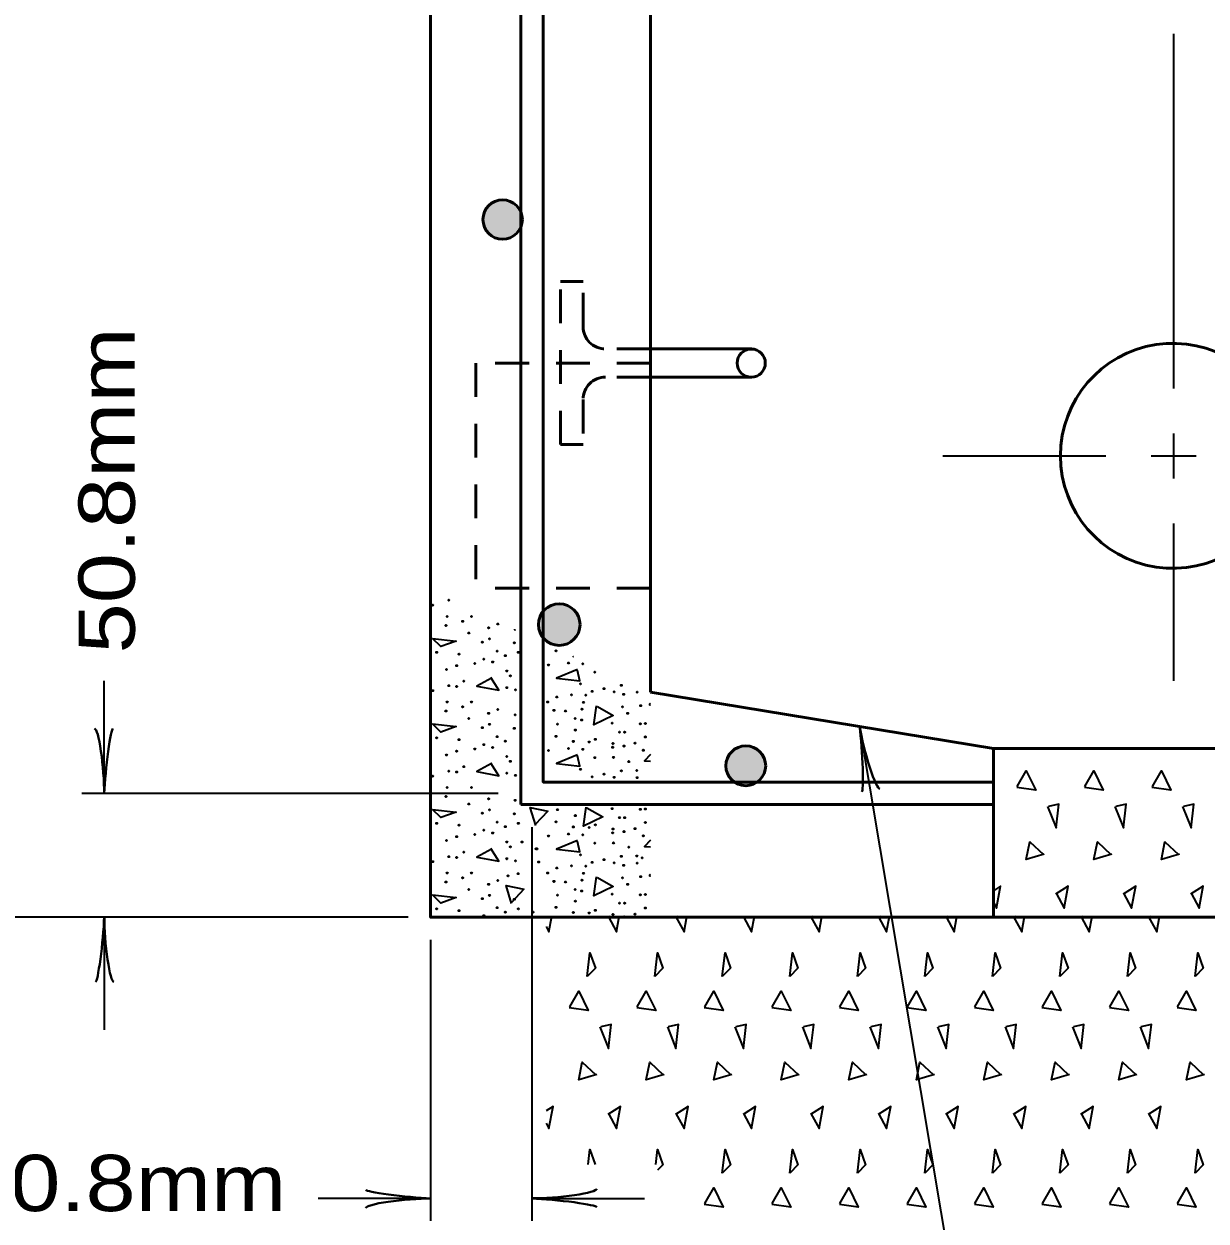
# Model space of a CAD drawing. Extents: x 918 to 1774, y -8 to 536.
# Drawn here: x 1039.5 to 1102.6, y 129.8 to 193.7 of the extents above; entities that cross this region are included whole.
import ezdxf

# ---------------------------------------------------------------- set-up
doc = ezdxf.new("R2010")
doc.units = 0
doc.header["$LTSCALE"] = 1.2
doc.linetypes.add('SHORT_DASHED', pattern=[2.7, 1.5, -1.2])
doc.layers.add('1', color=7, linetype='Continuous', lineweight=35)

msp = doc.modelspace()

# ---------------------------------------------------------------- hatches: boundary and pattern name
at = {"layer": '1'}
for points in [[(1066.115, 183.245, 1), (1064.014, 183.245, 1)], [(1069.19, 161.645, 1), (1066.973, 161.645, 1)], [(1079.087, 154.116, 1), (1076.963, 154.116, 1)]]:
    msp.add_hatch(color=256, dxfattribs=at).paths.add_polyline_path(points)

# ---------------------------------------------------------------- linework, layer by layer
at = {"layer": '1', "lineweight": 53}
for p, q in [((1061.227, 198.122), (1061.227, 163.476)), ((1072.952, 198.122), (1072.952, 158.043)), ((1072.952, 176.343), (1078.351, 176.343)), ((1072.952, 174.843), (1078.351, 174.843)), ((1072.952, 158.043), (1091.227, 155.043)), ((1091.227, 155.043), (1110.428, 155.043)), ((1091.227, 155.043), (1091.227, 146.043)), ((1072.952, 146.043), (1127.291, 146.043))]:
    msp.add_line(p, q, dxfattribs=at)
at = {"layer": '1'}
for p, q in [((1100.828, 193.143), (1100.828, 174.243)), ((1100.828, 171.843), (1100.828, 169.443)), ((1088.528, 170.643), (1097.227, 170.643)), ((1099.628, 170.643), (1102.028, 170.643)), ((1100.828, 167.043), (1100.828, 158.643)), ((1043.828, 152.643), (1043.828, 158.643)), ((1064.828, 152.643), (1042.628, 152.643)), ((1066.628, 150.843), (1066.628, 129.843)), ((1060.028, 146.043), (1028.227, 146.043)), ((1043.828, 146.043), (1043.828, 140.043)), ((1070.8, 146.086), (1070.678, 146.007)), ((1074.4, 146.086), (1074.278, 146.007)), ((1078, 146.086), (1077.878, 146.007)), ((1081.6, 146.086), (1081.478, 146.007)), ((1085.2, 146.086), (1085.078, 146.007)), ((1088.8, 146.086), (1088.678, 146.007)), ((1092.4, 146.086), (1092.278, 146.007)), ((1096, 146.086), (1095.878, 146.007)), ((1099.6, 146.086), (1099.478, 146.007)), ((1061.227, 144.843), (1061.227, 129.843)), ((1061.227, 131.043), (1055.227, 131.043)), ((1066.628, 131.043), (1072.628, 131.043))]:
    msp.add_line(p, q, dxfattribs=at)
at = {"layer": '1', "linetype": 'SHORT_DASHED', "lineweight": 53}
for p, q in [((1069.351, 177.543), (1069.351, 179.943)), ((1072.952, 176.343), (1070.552, 176.343)), ((1072.952, 175.593), (1063.64, 175.593)), ((1063.64, 175.593), (1063.64, 163.593)), ((1072.952, 174.843), (1070.552, 174.843)), ((1069.351, 173.643), (1069.351, 171.243)), ((1068.151, 171.243), (1069.351, 171.243)), ((1072.952, 163.593), (1063.64, 163.593))]:
    msp.add_line(p, q, dxfattribs=at)
at = {"layer": '1', "lineweight": 53}
msp.add_lwpolyline([(1066.028, 152.043), (1066.028, 224.745), (1067.227, 224.745), (1067.227, 153.243), (1091.227, 153.243), (1091.227, 152.043)], close=True, dxfattribs=at)
at = {"layer": '1', "linetype": 'SHORT_DASHED', "lineweight": 53}
msp.add_lwpolyline([(1068.151, 171.243), (1068.151, 179.943), (1069.351, 179.943)], dxfattribs=at)
at = {"layer": '1', "lineweight": 53}
msp.add_lwpolyline([(1072.952, 146.043), (1061.227, 146.043), (1061.227, 163.476)], dxfattribs=at)
at = {"layer": '1'}
for points in [[(1061.227, 163.452), (1061.235, 163.452), (1061.227, 163.468)], [(1069.059, 159.252), (1067.931, 158.796), (1069.179, 158.652), (1069.059, 159.204)], [(1061.227, 158.892), (1061.235, 158.892), (1061.227, 158.908)], [(1064.475, 158.796), (1063.683, 158.364), (1064.859, 158.148), (1064.427, 158.82)], [(1070.115, 157.284), (1070.955, 156.804), (1069.923, 156.3), (1070.067, 157.308)], [(1084.092, 156.215), (1093.824, 98.076), (1086.695, 98.076)], [(1069.059, 154.692), (1067.931, 154.236), (1069.179, 154.092), (1069.059, 154.644)], [(1072.952, 154.713), (1072.635, 154.38), (1072.952, 154.358)], [(1061.227, 154.332), (1061.235, 154.332), (1061.227, 154.348)], [(1064.475, 154.236), (1063.683, 153.804), (1064.859, 153.588), (1064.427, 154.26)], [(1092.5, 153.007), (1092.98, 153.847), (1093.484, 152.815), (1092.476, 152.959)], [(1096.1, 153.007), (1096.58, 153.847), (1097.084, 152.815), (1096.076, 152.959)], [(1099.7, 153.007), (1100.18, 153.847), (1100.684, 152.815), (1099.676, 152.959)], [(1094.108, 151.951), (1094.564, 150.799), (1094.708, 152.071), (1094.156, 151.951)], [(1097.708, 151.951), (1098.164, 150.799), (1098.308, 152.071), (1097.756, 151.951)], [(1101.308, 151.951), (1101.764, 150.799), (1101.908, 152.071), (1101.356, 151.951)], [(1066.828, 150.929), (1066.54, 151.889), (1067.476, 151.697), (1066.804, 150.977)], [(1069.561, 151.88), (1070.4, 151.4), (1069.369, 150.896), (1069.513, 151.904)], [(1069.059, 150.132), (1067.931, 149.676), (1069.179, 149.532), (1069.059, 150.084)], [(1072.952, 150.153), (1072.635, 149.82), (1072.952, 149.798)], [(1093.94, 149.406), (1092.98, 149.119), (1093.172, 150.055), (1093.892, 149.382)], [(1097.54, 149.406), (1096.58, 149.119), (1096.772, 150.055), (1097.492, 149.382)], [(1101.14, 149.406), (1100.18, 149.119), (1100.372, 150.055), (1101.092, 149.382)], [(1061.227, 149.772), (1061.235, 149.772), (1061.227, 149.788)], [(1064.475, 149.676), (1063.683, 149.244), (1064.859, 149.028), (1064.427, 149.7)], [(1070.115, 148.164), (1070.955, 147.684), (1069.923, 147.18), (1070.067, 148.188)], [(1065.541, 146.768), (1065.253, 147.728), (1066.189, 147.536), (1065.517, 146.816)], [(1091.227, 146.836), (1091.396, 146.526), (1091.612, 147.703), (1091.227, 147.455)], [(1094.564, 147.319), (1094.996, 146.526), (1095.212, 147.703), (1094.54, 147.27)], [(1098.164, 147.319), (1098.596, 146.526), (1098.812, 147.703), (1098.14, 147.27)], [(1101.764, 147.319), (1102.196, 146.526), (1102.412, 147.703), (1101.74, 147.27)], [(1067.382, 145.542), (1067.534, 145.263), (1067.685, 146.086)], [(1070.702, 146.055), (1071.134, 145.263), (1071.285, 146.086)], [(1074.302, 146.055), (1074.734, 145.263), (1074.885, 146.086)], [(1077.902, 146.055), (1078.334, 145.263), (1078.485, 146.086)], [(1081.502, 146.055), (1081.934, 145.263), (1082.085, 146.086)], [(1085.102, 146.055), (1085.534, 145.263), (1085.685, 146.086)], [(1088.702, 146.055), (1089.134, 145.263), (1089.285, 146.086)], [(1092.302, 146.055), (1092.734, 145.263), (1092.885, 146.086)], [(1095.902, 146.055), (1096.334, 145.263), (1096.485, 146.086)], [(1099.502, 146.055), (1099.934, 145.263), (1100.085, 146.086)], [(1068.638, 141.255), (1069.118, 142.095), (1069.622, 141.063), (1068.614, 141.207)], [(1072.238, 141.255), (1072.718, 142.095), (1073.222, 141.063), (1072.214, 141.207)], [(1075.838, 141.255), (1076.318, 142.095), (1076.822, 141.063), (1075.814, 141.207)], [(1079.438, 141.255), (1079.918, 142.095), (1080.422, 141.063), (1079.414, 141.207)], [(1083.038, 141.255), (1083.518, 142.095), (1084.022, 141.063), (1083.014, 141.207)], [(1086.638, 141.255), (1087.118, 142.095), (1087.622, 141.063), (1086.614, 141.207)], [(1090.238, 141.255), (1090.718, 142.095), (1091.222, 141.063), (1090.214, 141.207)], [(1093.838, 141.255), (1094.318, 142.095), (1094.822, 141.063), (1093.814, 141.207)], [(1097.438, 141.255), (1097.918, 142.095), (1098.422, 141.063), (1097.414, 141.207)], [(1101.038, 141.255), (1101.518, 142.095), (1102.022, 141.063), (1101.014, 141.207)], [(1070.246, 140.199), (1070.702, 139.047), (1070.846, 140.319), (1070.294, 140.199)], [(1073.846, 140.199), (1074.302, 139.047), (1074.446, 140.319), (1073.894, 140.199)], [(1077.446, 140.199), (1077.902, 139.047), (1078.046, 140.319), (1077.494, 140.199)], [(1081.046, 140.199), (1081.502, 139.047), (1081.646, 140.319), (1081.094, 140.199)], [(1084.646, 140.199), (1085.102, 139.047), (1085.246, 140.319), (1084.694, 140.199)], [(1088.246, 140.199), (1088.702, 139.047), (1088.846, 140.319), (1088.294, 140.199)], [(1091.846, 140.199), (1092.302, 139.047), (1092.446, 140.319), (1091.894, 140.199)], [(1095.446, 140.199), (1095.902, 139.047), (1096.046, 140.319), (1095.494, 140.199)], [(1099.046, 140.199), (1099.502, 139.047), (1099.646, 140.319), (1099.094, 140.199)], [(1070.078, 137.655), (1069.118, 137.367), (1069.31, 138.303), (1070.03, 137.631)], [(1073.678, 137.655), (1072.718, 137.367), (1072.91, 138.303), (1073.63, 137.631)], [(1077.278, 137.655), (1076.318, 137.367), (1076.51, 138.303), (1077.23, 137.631)], [(1080.878, 137.655), (1079.918, 137.367), (1080.11, 138.303), (1080.83, 137.631)], [(1084.478, 137.655), (1083.518, 137.367), (1083.71, 138.303), (1084.43, 137.631)], [(1088.078, 137.655), (1087.118, 137.367), (1087.31, 138.303), (1088.03, 137.631)], [(1091.678, 137.655), (1090.718, 137.367), (1090.91, 138.303), (1091.63, 137.631)], [(1095.278, 137.655), (1094.318, 137.367), (1094.51, 138.303), (1095.23, 137.631)], [(1098.878, 137.655), (1097.918, 137.367), (1098.11, 138.303), (1098.83, 137.631)], [(1102.478, 137.655), (1101.518, 137.367), (1101.71, 138.303), (1102.43, 137.631)], [(1067.382, 135.054), (1067.534, 134.775), (1067.75, 135.951), (1067.382, 135.715)], [(1070.702, 135.567), (1071.134, 134.775), (1071.35, 135.951), (1070.678, 135.519)], [(1074.302, 135.567), (1074.734, 134.775), (1074.95, 135.951), (1074.278, 135.519)], [(1077.902, 135.567), (1078.334, 134.775), (1078.55, 135.951), (1077.878, 135.519)], [(1081.502, 135.567), (1081.934, 134.775), (1082.15, 135.951), (1081.478, 135.519)], [(1085.102, 135.567), (1085.534, 134.775), (1085.75, 135.951), (1085.078, 135.519)], [(1088.702, 135.567), (1089.134, 134.775), (1089.35, 135.951), (1088.678, 135.519)], [(1092.302, 135.567), (1092.734, 134.775), (1092.95, 135.951), (1092.278, 135.519)], [(1095.902, 135.567), (1096.334, 134.775), (1096.55, 135.951), (1095.878, 135.519)], [(1099.502, 135.567), (1099.934, 134.775), (1100.15, 135.951), (1099.478, 135.519)], [(1069.626, 132.853), (1069.718, 133.647), (1069.998, 132.853)], [(1073.226, 132.853), (1073.318, 133.647), (1073.606, 132.831), (1073.322, 132.547)], [(1075.838, 130.767), (1076.318, 131.607), (1076.822, 130.575), (1075.814, 130.719)], [(1079.438, 130.767), (1079.918, 131.607), (1080.422, 130.575), (1079.414, 130.719)], [(1083.038, 130.767), (1083.518, 131.607), (1084.022, 130.575), (1083.014, 130.719)], [(1086.638, 130.767), (1087.118, 131.607), (1087.622, 130.575), (1086.614, 130.719)], [(1090.238, 130.767), (1090.718, 131.607), (1091.222, 130.575), (1090.214, 130.719)], [(1093.838, 130.767), (1094.318, 131.607), (1094.822, 130.575), (1093.814, 130.719)], [(1097.438, 130.767), (1097.918, 131.607), (1098.422, 130.575), (1097.414, 130.719)], [(1101.038, 130.767), (1101.518, 131.607), (1102.022, 130.575), (1101.014, 130.719)]]:
    msp.add_lwpolyline(points, dxfattribs=at)
for points in [[(1061.331, 160.908), (1062.579, 160.764), (1061.763, 160.476)], [(1061.331, 156.348), (1062.579, 156.204), (1061.763, 155.916)], [(1061.331, 151.788), (1062.579, 151.644), (1061.763, 151.356)], [(1061.331, 147.228), (1062.579, 147.084), (1061.763, 146.796)], [(1069.574, 142.887), (1069.718, 144.135), (1070.006, 143.319)], [(1073.174, 142.887), (1073.318, 144.135), (1073.606, 143.319)], [(1076.774, 142.887), (1076.918, 144.135), (1077.206, 143.319)], [(1080.374, 142.887), (1080.518, 144.135), (1080.806, 143.319)], [(1083.974, 142.887), (1084.118, 144.135), (1084.406, 143.319)], [(1087.574, 142.887), (1087.718, 144.135), (1088.006, 143.319)], [(1091.174, 142.887), (1091.318, 144.135), (1091.606, 143.319)], [(1094.774, 142.887), (1094.918, 144.135), (1095.206, 143.319)], [(1098.374, 142.887), (1098.518, 144.135), (1098.806, 143.319)], [(1101.974, 142.887), (1102.118, 144.135), (1102.406, 143.319)], [(1076.774, 132.399), (1076.918, 133.647), (1077.206, 132.831)], [(1080.374, 132.399), (1080.518, 133.647), (1080.806, 132.831)], [(1083.974, 132.399), (1084.118, 133.647), (1084.406, 132.831)], [(1087.574, 132.399), (1087.718, 133.647), (1088.006, 132.831)], [(1091.174, 132.399), (1091.318, 133.647), (1091.606, 132.831)], [(1094.774, 132.399), (1094.918, 133.647), (1095.206, 132.831)], [(1098.374, 132.399), (1098.518, 133.647), (1098.806, 132.831)], [(1101.974, 132.399), (1102.118, 133.647), (1102.406, 132.831)]]:
    msp.add_lwpolyline(points, close=True, dxfattribs=at)
at = {"layer": '1', "lineweight": 53}
for centre, radius in [((1065.065, 183.245), 1.05), ((1078.317, 175.591), 0.75), ((1068.082, 161.645), 1.109), ((1078.025, 154.116), 1.062)]:
    msp.add_circle(centre, radius, dxfattribs=at)
at = {"layer": '1'}
for centre in [(1062.2, 162.951), (1061.341, 162.68), (1062.041, 161.599), (1062.104, 162.076), (1062.931, 161.821), (1063.408, 162.076), (1064.808, 161.678), (1063.265, 161.201), (1064.315, 161.471), (1064.363, 160.883), (1063.981, 160.708), (1064.776, 160.23), (1065.683, 160.676), (1067.909, 160.246), (1061.548, 160.167), (1062.74, 160.071), (1064.06, 159.801), (1064.537, 159.648), (1065.205, 159.992), (1065.905, 160.167), (1068.577, 159.6), (1062.072, 159.25), (1062.613, 159.457), (1063.583, 159.568), (1065.285, 159.17), (1067.511, 159.489), (1069.34, 159.552), (1069.977, 159.107), (1062.2, 158.391), (1062.613, 158.343), (1062.995, 158.63), (1065.476, 158.916), (1069.213, 158.486), (1071.392, 158.407), (1061.341, 158.12), (1065.285, 158.279), (1065.746, 158.168), (1067.957, 157.786), (1068.736, 157.898), (1069.499, 157.882), (1069.833, 158.089), (1070.47, 158.232), (1071.01, 158.057), (1071.519, 157.929), (1072.235, 158.041), (1062.041, 157.039), (1062.104, 157.516), (1062.931, 157.261), (1063.408, 157.516), (1064.808, 157.118), (1067.464, 157.516), (1067.798, 157.07), (1068.418, 157.039), (1069.293, 157.134), (1069.372, 157.5), (1071.456, 157.261), (1072.426, 157.325), (1063.265, 156.641), (1064.315, 156.911), (1065.73, 156.832), (1068.927, 156.641), (1069.277, 156.561), (1070.899, 156.386), (1071.726, 156.911), (1063.981, 156.148), (1064.363, 156.323), (1065.683, 156.116), (1067.989, 156.339), (1068.943, 156.02), (1071.297, 155.909), (1071.567, 155.909), (1072.402, 156.352), (1072.673, 156.37), (1061.548, 155.607), (1062.74, 155.511), (1064.06, 155.241), (1064.776, 155.67), (1065.205, 155.432), (1067.909, 155.686), (1068.832, 155.416), (1069.674, 155.384), (1070.008, 155.527), (1070.931, 155.104), (1070.947, 155.305), (1071.535, 155.167), (1072.124, 155.32), (1072.673, 155.655), (1062.072, 154.69), (1062.613, 154.897), (1063.583, 155.008), (1064.537, 155.088), (1065.285, 154.61), (1067.511, 154.929), (1068.577, 155.04), (1069.34, 154.992), (1069.977, 154.547), (1070.978, 154.563), (1072.562, 154.944), (1062.2, 153.831), (1062.995, 154.07), (1065.476, 154.356), (1069.213, 153.926), (1071.392, 153.847), (1071.79, 154.34), (1072.219, 153.863), (1061.341, 153.56), (1062.613, 153.783), (1065.285, 153.719), (1065.746, 153.608), (1069.833, 153.529), (1070.47, 153.672), (1071.01, 153.497), (1072.235, 153.481), (1062.104, 152.956), (1063.408, 152.956), (1062.041, 152.479), (1063.265, 152.081), (1064.315, 152.351), (1065.73, 152.272), (1063.981, 151.588), (1064.363, 151.763), (1065.683, 151.556), (1067.989, 151.779), (1068.943, 151.46), (1070.899, 151.826), (1071.297, 151.349), (1071.567, 151.349), (1072.402, 151.792), (1072.673, 151.81), (1061.548, 151.047), (1062.74, 150.951), (1064.06, 150.681), (1064.776, 151.11), (1065.205, 150.872), (1065.905, 151.047), (1067.909, 151.126), (1068.832, 150.856), (1069.674, 150.824), (1070.008, 150.967), (1070.947, 150.745), (1072.124, 150.76), (1072.673, 151.095), (1062.072, 150.13), (1062.613, 150.337), (1063.583, 150.448), (1064.537, 150.528), (1065.285, 150.05), (1066.096, 150.05), (1067.511, 150.369), (1068.577, 150.48), (1069.34, 150.432), (1070.931, 150.544), (1070.978, 150.003), (1071.535, 150.607), (1072.562, 150.384), (1062.995, 149.51), (1065.476, 149.796), (1066.844, 149.685), (1066.907, 149.685), (1069.213, 149.366), (1069.977, 149.987), (1071.79, 149.78), (1061.341, 149), (1062.2, 149.271), (1062.613, 149.223), (1065.285, 149.159), (1065.746, 149.048), (1066.987, 148.984), (1068.736, 148.778), (1069.499, 148.762), (1069.833, 148.969), (1070.47, 149.112), (1071.01, 148.937), (1071.392, 149.287), (1071.519, 148.809), (1072.219, 149.303), (1072.235, 148.921), (1072.499, 149.207), (1062.104, 148.396), (1062.931, 148.141), (1063.408, 148.396), (1065.353, 148.245), (1065.889, 148.364), (1067.464, 148.396), (1067.957, 148.666), (1069.372, 148.38), (1071.456, 148.141), (1072.426, 148.205), (1062.041, 147.919), (1063.265, 147.521), (1064.315, 147.791), (1064.808, 147.998), (1067.798, 147.95), (1068.418, 147.919), (1068.927, 147.521), (1069.277, 147.441), (1069.293, 148.014), (1071.726, 147.791), (1063.981, 147.028), (1064.363, 147.203), (1065.683, 146.996), (1067.989, 147.219), (1068.943, 146.9), (1070.899, 147.266), (1072.402, 147.232), (1072.673, 147.25), (1061.548, 146.487), (1062.74, 146.391), (1064.776, 146.55), (1065.205, 146.312), (1065.905, 146.487), (1066.684, 146.312), (1067.909, 146.566), (1068.832, 146.296), (1069.674, 146.264), (1070.008, 146.407), (1070.947, 146.185), (1071.297, 146.789), (1071.567, 146.789), (1072.124, 146.2), (1072.673, 146.535), (1064.06, 146.121)]:
    msp.add_circle(centre, 0.0318, dxfattribs=at)
at = {"layer": '1', "linetype": 'SHORT_DASHED', "lineweight": 53}
for centre, start, end in [((1070.552, 177.543), 180, 270), ((1070.552, 173.643), 90, 180)]:
    msp.add_arc(centre, 1.2, start, end, dxfattribs=at)
at = {"layer": '1', "lineweight": 53}
msp.add_arc((1100.802, 170.644), 6, 17.38217, 342.61783, dxfattribs=at)
at = {"layer": '1'}
for centre, start, end in [((1061.229, 161.328), 266.41343, 93.58658), ((1065.73, 161.392), 158.73033, 331.54608), ((1068.832, 159.976), 197.15661, 293.1198), ((1072.928, 157.389), 41.80177, 318.19823), ((1061.229, 156.768), 266.41343, 93.58658), ((1061.229, 152.208), 266.41343, 93.58658), ((1072.928, 148.269), 41.80177, 318.19823), ((1061.229, 147.648), 266.41343, 93.58658), ((1071.535, 146.047), 353.24736, 186.75264)]:
    msp.add_arc(centre, 0.0318, start, end, dxfattribs=at)
at = {"layer": '1', "lineweight": 40}
for centre, major_axis, ratio, start_param, end_param in [((1043.496, 153.953), (0.187, -2.143), 0.122415, 0.896353, 3.141593), ((1043.496, 153.953), (0.187, -2.143), 0.122415, 0.896353, 3.141593), ((1044.081, 153.988), (-0.211, -2.108), 0.07063, 3.140715, 5.41811), ((1044.081, 153.988), (-0.211, -2.108), 0.07063, 3.140715, 5.41811), ((1084.064, 154.847), (0.14, -2.114), 0.07063, 6.282307, 8.559703), ((1084.636, 154.978), (-0.539, 2.083), 0.122415, 0.896353, 3.141593), ((1043.574, 144.699), (0.211, 2.108), 0.07063, 3.140715, 5.41811), ((1043.574, 144.699), (0.211, 2.108), 0.07063, 3.140715, 5.41811), ((1044.159, 144.734), (-0.187, 2.143), 0.122415, 0.896353, 3.141593), ((1044.159, 144.734), (-0.187, 2.143), 0.122415, 0.896353, 3.141593), ((1067.937, 131.375), (-2.143, -0.187), 0.122415, 0.896353, 3.141593), ((1067.937, 131.375), (-2.143, -0.187), 0.122415, 0.896353, 3.141593), ((1059.918, 130.712), (2.143, 0.187), 0.122415, 0.896353, 3.141593), ((1059.918, 130.712), (2.143, 0.187), 0.122415, 0.896353, 3.141593), ((1059.883, 131.297), (2.108, -0.211), 0.07063, 3.140715, 5.41811), ((1059.883, 131.297), (2.108, -0.211), 0.07063, 3.140715, 5.41811), ((1067.972, 130.789), (-2.108, 0.211), 0.07063, 3.140715, 5.41811), ((1067.972, 130.789), (-2.108, 0.211), 0.07063, 3.140715, 5.41811)]:
    msp.add_ellipse(centre, major_axis=major_axis, ratio=ratio, start_param=start_param, end_param=end_param, dxfattribs=at)

# ---------------------------------------------------------------- texts
at = {"layer": '1', "width": 1.2}
msp.add_text('50.8mm', height=3, rotation=90, dxfattribs=at).set_placement((1045.455, 160.106))
msp.add_text('50.8mm', height=3, dxfattribs=at).set_placement((1036.135, 130.368))

doc.saveas('drawing.dxf')
